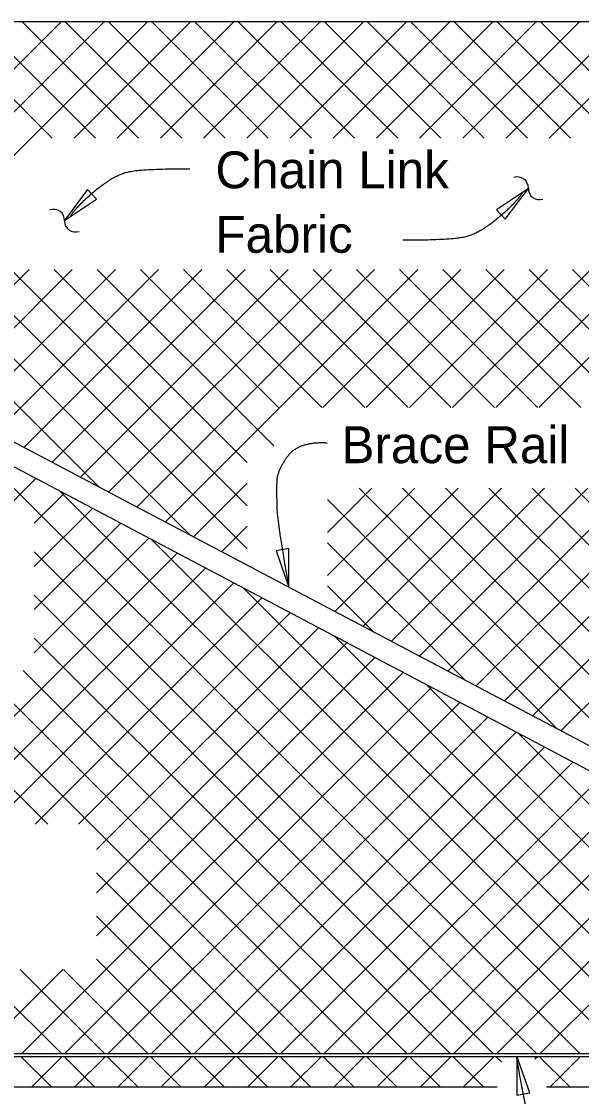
# Model space of a CAD drawing. Extents: x 0 to 41.2, y 0 to 26.
# Drawn here: x 16.23 to 19.28, y 17.08 to 22.95 of the extents above; entities that cross this region are included whole.
import ezdxf

# ---------------------------------------------------------------- set-up
doc = ezdxf.new("R2010")
doc.units = 0
for name, color, linetype in [('Dimension', 7, 'Continuous'), ('Miscellaneous', 7, 'Continuous'), ('SteelMisc', 7, 'Continuous'), ('SupstrConc', 7, 'Continuous'), ('TextStructures', 7, 'Continuous')]:
    doc.layers.add(name, color=color, linetype=linetype)

msp = doc.modelspace()

# ---------------------------------------------------------------- linework, layer by layer
at = {"layer": 'Dimension'}
for points in [[(16.4595, 21.8673), (16.6347, 21.9852), (16.5861, 22.0364)], [(18.9917, 22.0434), (18.8164, 21.9255), (18.865, 21.8743)], [(17.684, 19.8645), (17.6836, 20.0757), (17.6141, 20.0638)], [(18.9273, 17.3029), (18.9289, 17.0916), (18.9983, 17.1039)]]:
    msp.add_lwpolyline(points, close=True, dxfattribs=at)
for centre, start, end in [((18.9315, 22.0462), 357.71778, 109.44499), ((19.0506, 22.0414), 177.71778, 289.44499), ((16.4004, 21.8692), 357.71778, 109.44499), ((16.5195, 21.8645), 177.71778, 289.44499)]:
    msp.add_arc(centre, 0.0596, start, end, dxfattribs=at)
for points in [[(17.1447, 22.149), (16.8545, 22.149), (16.7179, 22.1042), (16.5309, 21.9506), (16.4925, 21.893)], [(18.3063, 21.7616), (18.5965, 21.7616), (18.7331, 21.8064), (18.9201, 21.96), (18.9585, 22.0176)], [(17.894, 20.6524), (17.7375, 20.6606), (17.6194, 20.5021), (17.6164, 20.3809), (17.6211, 20.2132), (17.6839, 19.8645)], [(18.6159, 16.5559), (18.8387, 16.5523), (18.9236, 16.5913), (19.0545, 16.74), (18.9696, 17.0374), (18.9272, 17.3027)]]:
    msp.add_open_spline(points, degree=2, dxfattribs=at)
at = {"layer": 'Miscellaneous'}
for p, q in [((14.1054, 22.9547), (16.6484, 20.4117)), ((14.3411, 22.9547), (17.1483, 20.1475)), ((14.5768, 22.9547), (17.4573, 20.0742)), ((14.8125, 22.9547), (17.4573, 20.3099)), ((14.85, 21.362), (16.4427, 22.9547)), ((15.0042, 21.2805), (16.6784, 22.9547)), ((15.1584, 21.199), (16.9141, 22.9547)), ((15.7553, 22.9547), (16.393, 22.317)), ((15.991, 22.9547), (16.6287, 22.317)), ((16.2267, 22.9547), (16.8644, 22.317)), ((16.4624, 22.9547), (17.1001, 22.317)), ((16.5121, 22.317), (17.1498, 22.9547)), ((16.6981, 22.9547), (17.3358, 22.317)), ((16.7478, 22.317), (17.3855, 22.9547)), ((16.9338, 22.9547), (17.5715, 22.317)), ((16.9835, 22.317), (17.6212, 22.9547)), ((17.1695, 22.9547), (17.8072, 22.317)), ((17.2192, 22.317), (17.8569, 22.9547)), ((17.4052, 22.9547), (18.0429, 22.317)), ((17.4549, 22.317), (18.0926, 22.9547)), ((17.6409, 22.9547), (18.2786, 22.317)), ((17.6906, 22.317), (18.3283, 22.9547)), ((17.8766, 22.9547), (18.5143, 22.317)), ((17.9263, 22.317), (18.564, 22.9547)), ((18.1123, 22.9547), (18.75, 22.317)), ((18.162, 22.317), (18.7997, 22.9547)), ((18.348, 22.9547), (18.9857, 22.317)), ((18.3977, 22.317), (19.0354, 22.9547)), ((18.5775, 20.8468), (20.6853, 22.9547)), ((18.5837, 22.9547), (19.2214, 22.317)), ((18.6334, 22.317), (19.2711, 22.9547)), ((18.8132, 20.8468), (20.921, 22.9547)), ((18.8194, 22.9547), (22.0604, 19.7137)), ((18.8691, 22.317), (19.5068, 22.9547)), ((19.0489, 20.8468), (21.1567, 22.9547)), ((19.0551, 22.9547), (22.0604, 19.9494)), ((19.1049, 22.317), (19.7425, 22.9547)), ((18.7053, 19.3247), (22.0604, 22.6798)), ((18.8595, 19.2432), (22.0604, 22.4441)), ((19.0137, 19.1617), (22.0604, 22.2084)), ((19.1679, 19.0802), (22.0604, 21.9727)), ((15.6211, 20.9546), (16.2665, 21.6)), ((15.7753, 20.8731), (16.5022, 21.6)), ((15.7753, 20.8731), (16.5022, 21.6)), ((15.9295, 20.7916), (16.7379, 21.6)), ((15.9295, 20.7916), (16.7379, 21.6)), ((16.0837, 20.7101), (16.9736, 21.6)), ((16.0837, 20.7101), (16.9736, 21.6)), ((16.2379, 20.6286), (17.2093, 21.6)), ((16.2379, 20.6286), (17.2093, 21.6)), ((16.3921, 20.5471), (17.445, 21.6)), ((16.4029, 21.6), (17.4573, 20.5456)), ((16.5463, 20.4656), (17.6807, 21.6)), ((16.6386, 21.6), (17.6017, 20.6369)), ((16.7005, 20.3841), (17.9164, 21.6)), ((16.8547, 20.3026), (18.1521, 21.6)), ((16.8743, 21.6), (17.6275, 20.8468)), ((16.8743, 21.6), (17.6275, 20.8468)), ((17.009, 20.2211), (18.3878, 21.6)), ((17.11, 21.6), (17.8632, 20.8468)), ((17.3457, 21.6), (18.0989, 20.8468)), ((17.3457, 21.6), (18.0989, 20.8468)), ((17.3457, 21.6), (18.0989, 20.8468)), ((17.5814, 21.6), (18.3346, 20.8468)), ((17.5814, 21.6), (18.3346, 20.8468)), ((17.8171, 21.6), (18.5703, 20.8468)), ((17.8704, 20.8468), (18.6235, 21.6)), ((18.0528, 21.6), (18.806, 20.8468)), ((18.1061, 20.8468), (18.8592, 21.6)), ((18.2885, 21.6), (19.0417, 20.8468)), ((18.3418, 20.8468), (19.0949, 21.6)), ((18.5242, 21.6), (19.2774, 20.8468)), ((18.7599, 21.6), (19.5131, 20.8468)), ((18.9956, 21.6), (22.0604, 18.5352)), ((19.2313, 21.6), (22.0604, 18.7709)), ((15.9363, 20.6524), (19.2711, 17.3175)), ((16.0901, 20.2451), (16.3034, 20.4584)), ((17.1632, 20.1396), (17.4573, 20.4338)), ((16.2952, 20.2145), (16.4576, 20.3769)), ((16.4361, 20.3882), (19.5068, 17.3175)), ((17.8948, 19.9285), (18.3723, 20.4059)), ((17.8948, 20.1642), (18.1366, 20.4059)), ((17.9342, 19.7322), (18.608, 20.4059)), ((18.0684, 20.4059), (19.6475, 18.8268)), ((18.0684, 20.4059), (19.6475, 18.8268)), ((18.0884, 19.6507), (18.8437, 20.4059)), ((18.2426, 19.5692), (19.0794, 20.4059)), ((18.2426, 19.5692), (19.0794, 20.4059)), ((18.3041, 20.4059), (20.1474, 18.5626)), ((18.3968, 19.4877), (19.3151, 20.4059)), ((18.5398, 20.4059), (20.6472, 18.2985)), ((18.5398, 20.4059), (20.6472, 18.2985)), ((18.5398, 20.4059), (20.6472, 18.2985)), ((18.551, 19.4062), (19.5508, 20.4059)), ((18.7755, 20.4059), (21.1471, 18.0343)), ((18.7755, 20.4059), (21.1471, 18.0343)), ((19.0112, 20.4059), (21.6469, 17.7701)), ((19.2469, 20.4059), (22.0604, 17.5924)), ((17.8948, 20.3438), (19.1477, 19.0909)), ((16.2952, 19.9788), (16.6118, 20.2954)), ((16.2952, 19.7431), (16.766, 20.2139)), ((17.3174, 20.0581), (17.4573, 20.1981)), ((16.2952, 19.5074), (16.9202, 20.1324)), ((16.936, 20.1241), (19.7425, 17.3175)), ((17.8948, 20.1081), (18.6478, 19.3551)), ((15.5936, 18.5701), (17.0744, 20.0509)), ((16.2952, 20.0578), (19.0354, 17.3175)), ((15.8293, 18.5701), (17.2287, 19.9694)), ((16.065, 18.5701), (17.3829, 19.8879)), ((17.4358, 19.86), (19.9782, 17.3175)), ((17.8948, 19.8724), (18.148, 19.6192)), ((16.2952, 19.8221), (18.7997, 17.3175)), ((16.3007, 18.5701), (17.5371, 19.8064)), ((16.5364, 18.5701), (17.6913, 19.725)), ((16.6339, 18.4318), (17.8455, 19.6435)), ((16.2952, 19.5864), (18.564, 17.3175)), ((16.6339, 18.1961), (17.9997, 19.562)), ((17.9357, 19.5958), (20.2139, 17.3175)), ((16.6339, 17.9604), (18.1539, 19.4805)), ((15.5278, 19.4109), (16.3686, 18.5701)), ((15.7635, 19.4109), (17.8569, 17.3175)), ((15.9992, 19.4109), (18.0926, 17.3175)), ((16.2267, 17.3175), (18.3081, 19.399)), ((16.2349, 19.4109), (18.3283, 17.3175)), ((16.4624, 17.3175), (18.4623, 19.3175)), ((18.4355, 19.3317), (20.4496, 17.3175)), ((16.6981, 17.3175), (18.6166, 19.236)), ((16.9338, 17.3175), (18.7708, 19.1545)), ((17.1695, 17.3175), (18.925, 19.073)), ((18.9353, 19.0676), (20.6853, 17.3175)), ((17.4052, 17.3175), (19.0792, 18.9915)), ((17.6409, 17.3175), (19.2334, 18.91)), ((17.8766, 17.3175), (19.3876, 18.8285)), ((18.1123, 17.3175), (19.5418, 18.7471)), ((18.348, 17.3175), (19.696, 18.6656)), ((18.5837, 17.3175), (19.8502, 18.5841)), ((18.8194, 17.3175), (20.0045, 18.5026)), ((19.0551, 17.3175), (20.1587, 18.4211)), ((16.6339, 18.3049), (17.6212, 17.3175)), ((16.6339, 18.0692), (17.3855, 17.3175)), ((16.6339, 17.8335), (17.1498, 17.3175)), ((15.9825, 17.7777), (16.4427, 17.3175)), ((15.991, 17.3175), (16.4503, 17.7768)), ((16.2182, 17.7777), (16.6784, 17.3175)), ((16.4539, 17.7777), (16.9141, 17.3175)), ((16.2217, 17.3028), (16.3884, 17.1361)), ((16.281, 17.1361), (16.4476, 17.3028)), ((16.4575, 17.3028), (16.6241, 17.1361)), ((16.5167, 17.1361), (16.6833, 17.3028)), ((16.6932, 17.3028), (16.8598, 17.1361)), ((16.7524, 17.1361), (16.919, 17.3028)), ((16.9289, 17.3028), (17.0955, 17.1361)), ((16.9881, 17.1361), (17.1547, 17.3028)), ((17.1646, 17.3028), (17.3312, 17.1361)), ((17.2238, 17.1361), (17.3904, 17.3028)), ((17.4003, 17.3028), (17.5669, 17.1361)), ((17.4595, 17.1361), (17.6262, 17.3028)), ((17.636, 17.3028), (17.8026, 17.1361)), ((17.6952, 17.1361), (17.8619, 17.3028)), ((17.8717, 17.3028), (18.0383, 17.1361)), ((17.9309, 17.1361), (18.0976, 17.3028)), ((18.1074, 17.3028), (18.274, 17.1361)), ((18.1666, 17.1361), (18.3333, 17.3028)), ((18.3431, 17.3028), (18.5097, 17.1361)), ((18.4023, 17.1361), (18.569, 17.3028)), ((18.5788, 17.3028), (18.7454, 17.1361)), ((18.638, 17.1361), (18.8047, 17.3028)), ((18.8145, 17.3028), (18.8456, 17.2716)), ((19.0263, 17.2887), (19.0404, 17.3028)), ((19.0502, 17.3028), (19.2168, 17.1361)), ((19.1094, 17.1361), (19.2761, 17.3028))]:
    msp.add_line(p, q, dxfattribs=at)
at = {"layer": 'SteelMisc'}
for p, q in [((13.4503, 22.9547), (21.9119, 22.9547)), ((21.8588, 17.6582), (12.6092, 22.5462)), ((21.8029, 17.5522), (12.5532, 22.4401)), ((12.5141, 17.3028), (21.9119, 17.3028)), ((12.5154, 17.3175), (21.8852, 17.3175))]:
    msp.add_line(p, q, dxfattribs=at)
at = {"layer": 'SupstrConc'}
for p, q in [((12.3521, 17.1361), (18.8204, 17.1361)), ((19.0892, 17.1361), (22.0604, 17.1361))]:
    msp.add_line(p, q, dxfattribs=at)

# ---------------------------------------------------------------- texts
at = {"layer": 'Dimension'}
for s, p in [('Chain Link ', (17.2835, 22.0436)), ('Fabric ', (17.2835, 21.6916))]:
    msp.add_text(s, height=0.2016, dxfattribs=at).set_placement(p)
at = {"layer": 'TextStructures'}
msp.add_text('Brace Rail', height=0.2016, dxfattribs=at).set_placement((17.9713, 20.5425))

doc.saveas('drawing.dxf')
